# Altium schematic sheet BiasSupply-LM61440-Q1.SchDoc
size 431 x 279 mm; Date: Not shown in title block; ApprovedBy: Not shown in title block; CheckedBy: Not shown in title block; Author: Not shown in title block; CompanyName: Not shown in title block; Engineer: Not shown in title block; Organization: Not shown in title block; Address1: Not shown in title block; Address2: Not shown in title block; Address3: Not shown in title block; Address4: Not shown in title block; DocumentNumber: 2; Revision: Use project parameter SCH_Rev; SheetNumber: 2; SheetTotal: 3; PageSetup: Record=PageOptions¦CenterHorizontal=True¦CenterVertical=True¦PrintScale=1.00¦XCorrection=1.00¦YCorrection=1.00¦PrintKind=0¦BorderSize=5000000¦LeftOffset=0¦BottomOffset=0¦Orientation=2¦PaperLength=1000¦PaperWidth=1000¦Scale=100¦PaperSource=15¦PrintQuality=600¦MediaType=1¦DitherType=10¦PaperKind=Letter¦PrintScaleMode=1
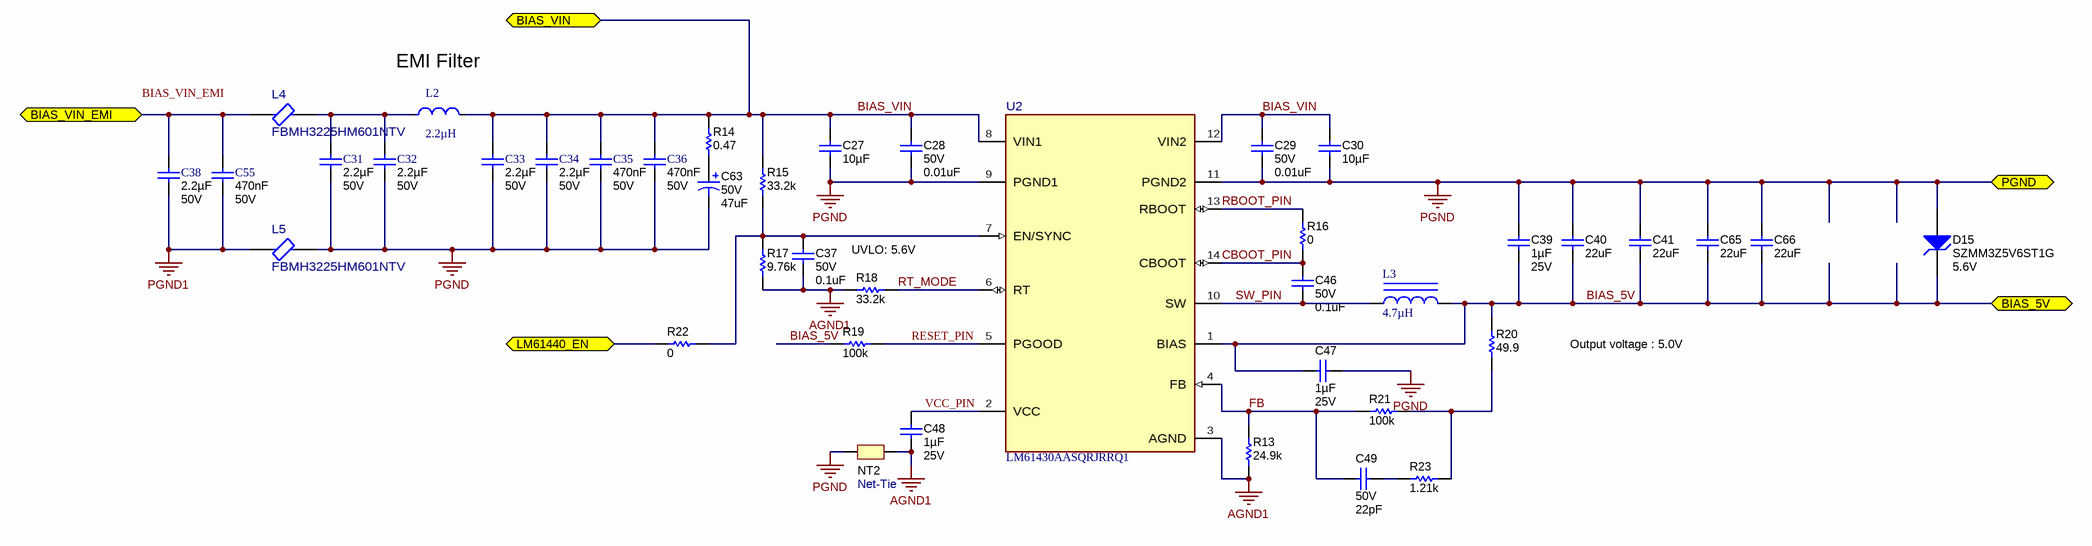
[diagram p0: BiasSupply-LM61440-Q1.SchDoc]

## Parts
C27  ValueDisplayed: 10µF  [1206_190]  (hidden comment: CGA5L1X7R1H106K160AC)
C28  VDC_V: 50V  ValueDisplayed: 0.01uF  [0402]  (hidden comment: CGA2B3X7R1H103K050BB)
C29  VDC_V: 50V  ValueDisplayed: 0.01uF  [0402]  (hidden comment: CGA2B3X7R1H103K050BB)
C30  ValueDisplayed: 10µF  [1206_190]  (hidden comment: CGA5L1X7R1H106K160AC)
C31  Cap_F: 2.2µF  VDC_V: 50V  [0805_HV]  (hidden comment: CF6)
C32  Cap_F: 2.2µF  VDC_V: 50V  [0805_HV]  (hidden comment: CF5)
C33  Cap_F: 2.2µF  VDC_V: 50V  [0805_HV]  (hidden comment: CF4)
C34  Cap_F: 2.2µF  VDC_V: 50V  [0805_HV]  (hidden comment: CF3)
C35  Cap_F: 470nF  VDC_V: 50V  [0603]  (hidden comment: CF2)
C36  Cap_F: 470nF  VDC_V: 50V  [0603]  (hidden comment: CF1)
C37  VDC_V: 50V  ValueDisplayed: 0.1uF  [0402]  (hidden comment: GCM155R71H104KE02D)
C38  Cap_F: 2.2µF  VDC_V: 50V  [0805_HV]  (hidden comment: CF6)
C39  Cap_F: 1µF  VDC_V: 25V  [0603S]  (hidden comment: CGA3E1X7R1E105K080AC)
C40  ValueDisplayed: 22uF  [1206_180]  (hidden comment: GCM31CR71A226KE02L)
C41  ValueDisplayed: 22uF  [1206_180]  (hidden comment: GCM31CR71A226KE02L)
C46  VDC_V: 50V  ValueDisplayed: 0.1uF  [0402]  (hidden comment: GCM155R71H104KE02D)
C47  Cap_F: 1µF  VDC_V: 25V  [0603S]  (hidden comment: CGA3E1X7R1E105K080AC)
C48  Cap_F: 1µF  VDC_V: 25V  [0603S]  (hidden comment: CGA3E1X7R1E105K080AC)
C49  VDC_V: 50V  ValueDisplayed: 22pF  [0402]  (hidden comment: CGA2B2NP01H220J050BA)
C55  Cap_F: 470nF  VDC_V: 50V  [0603]  (hidden comment: CF2)
C63  VDC_V: 50V  ValueDisplayed: 47uF  [SM_RADIAL_E]  (hidden comment: EEE-FK1H470P)
C65  ValueDisplayed: 22uF  [1206_180]  (hidden comment: GCM31CR71A226KE02L)
C66  ValueDisplayed: 22uF  [1206_180]  (hidden comment: GCM31CR71A226KE02L)
D15  SZMM3Z5V6ST1G  value 5.6V  [SOD-323]
L2  Ind_H: 2.2µH  [FP-744316220_SMD2-MFG]  (hidden comment: 744316220)
L3  ValueDisplayed: 4.7µH  [WE-XHMI_6060]  (hidden comment: 74439346047)
L4  FBMH3225HM601NTV  [FP-FBMH3225HM601NTV_1210-MFG]
L5  FBMH3225HM601NTV  [FP-FBMH3225HM601NTV_1210-MFG]
NT2  Net-Tie  [Net-Tie_10mil]  (net tie, no BOM)
R13  ValueDisplayed: 24.9k  [0402]  (hidden comment: CRCW040224K9FKED)
R14  ValueDisplayed: 0.47  [0805_HV]  (hidden comment: ERJ-6RQFR47V)
R15  ValueDisplayed: 33.2k  [0402]  (hidden comment: CRCW040233K2FKED)
R16  ValueDisplayed: 0  [0402]  (hidden comment: CRCW04020000Z0ED)
R17  ValueDisplayed: 9.76k  [0402]  (hidden comment: CRCW04029K76FKED)
R18  ValueDisplayed: 33.2k  [0402]  (hidden comment: CRCW040233K2FKED)
R19  ValueDisplayed: 100k  [0402]  (hidden comment: CRCW0402100KDHEDP)
R20  ValueDisplayed: 49.9  [0402]  (hidden comment: CRCW040249R9FKED)
R21  ValueDisplayed: 100k  [0402]  (hidden comment: CRCW0402100KDHEDP)
R22  ValueDisplayed: 0  [0402]  (hidden comment: CRCW04020000Z0ED)
R23  ValueDisplayed: 1.21k  [0402]  (hidden comment: CRCW04021K21FKED)
U2  LM61430AASQRJRRQ1  [RJR0014A-MFG]

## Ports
BIAS_5V (bidir), BIAS_VIN (bidir), BIAS_VIN_EMI (bidir), LM61440_EN (bidir), PGND (bidir)

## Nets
AGND1: C37.2 C48.2 NT2.2 R13.1 R17.1 R18.1 U2.3(AGND)
PGND: C27.2 C28.2 C29.2 C30.2 C31.2 C32.2 C33.2 C34.2 C35.2 C36.2 C39.2 C40.1 C41.1 C47.2 C63.2(-) C65.1 C66.1 D15.2(A) L5.2 NT2.1 U2.9(PGND1) U2.11(PGND2) ; port PGND
PGND1: C38.2 C55.2 L5.1
BIAS_5V: C39.1 C40.2 C41.2 C47.1 C65.2 C66.2 D15.1(K) L3.2 R19.1 R20.2 U2.1(BIAS) ; port BIAS_5V
BIAS_VIN: C27.1 C28.1 C29.1 C30.1 C33.1 C34.1 C35.1 C36.1 L2.2 R14.2 R15.2 U2.8(VIN1) U2.12(VIN2) ; port BIAS_VIN
BIAS_VIN_EMI: C38.1 C55.1 L4.1 ; port BIAS_VIN_EMI
CBOOT_PIN: C46.1 R16.1 U2.14(CBOOT)
FB: C49.2 R13.2 R21.1 U2.4(FB)
LM61440_EN: R22.1 ; port LM61440_EN
RBOOT_PIN: R16.2 U2.13(RBOOT)
RESET_PIN: R19.2 U2.5(PGOOD)
RT_MODE: R18.2 U2.6(RT)
SW_PIN: C46.2 L3.1 U2.10(SW)
VCC_PIN: C48.1 U2.2(VCC)
NetC31_1: C31.1 C32.1 L2.1 L4.2
NetC37_1: C37.1 R15.1 R17.2 R22.2 U2.7(EN/SYNC)
NetC49_1: C49.1 R23.2
NetC63_1: C63.1(+) R14.1
NetR20_1: R20.1 R21.2 R23.1

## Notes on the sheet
- (near L2) EMI Filter
- UVLO: 5.6V
- Output voltage : 5.0V
- Labels drawn without touching a wire or pin: BIAS_VIN_EMI

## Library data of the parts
C27 C30 = CMP-0085950-1: CAP, CERM, 10 µF, 50 V,+/- 10%, X7R, AEC-Q200 Grade 1, 1206; Manufacturer: TDK; SizeZ_mm: 1.9; Value: 10uF; Value2: 50V; Cap_Case: 1206; AEC Grade: 1; TaMin_C: -55°C; U/M: EA; SizeArea_mm2: 5.12; TaMax_C: 125°C; AEC Qualified: Y; AEC Category: Q200; SizeX_mm: 3.2; SizeY_mm: 1.6; Polarized: N; SizeAreaWB_mm2: 10.92
C28 C29 = CMP-0006324-2: CAP, CERM, 0.01 uF, 50 V, +/- 10%, X7R, AEC-Q200 Grade 1, 0402; Manufacturer: TDK; TaMin_C: -55°C; ESR_ohm: 0.333065; Polarized: N; SizeAreaWB_mm2: 3; Value1: 0.333065 ohm; U/M: EA; Value: 0.01uF; TaMax_C: 125°C; SizeZ_mm: 0.6; SizeX_mm: 1; SizeY_mm: 0.5; AEC Qualified: Y; Cap_F: 10nF; IRMS_A: 323.373mA; AEC Category: Q200
C31-C34 C38 = CMP-0007977-2: CAP, CERM, 2.2 uF, 50 V, +/- 10%, X7R, AEC-Q200 Grade 1, 0805; Manufacturer: TDK; PartNumber: CGA4J3X7R1H225K125AB; TaMin_C: -55°C; ESR_ohm: 3.288m; Polarized: N; SizeAreaWB_mm2: 6.75; Value1: 0.003288 ohm; U/M: EA; Value: 2.2uF; TaMax_C: 125°C; SizeZ_mm: 1.45; SizeX_mm: 2; SizeY_mm: 1.25; Cap_Case: 0805; SizeArea_mm2: 2.5; CompType: Capacitor; AEC Qualified: Y; IRMS_A: 3.60029A; AEC Grade: 1; AEC Category: Q200
C35 C36 C55 = CMP-0007097-4: CAP, CERM, 0.47 uF, 50 V, +/- 10%, X7R, AEC-Q200 Grade 1, 0603; Manufacturer: TDK; PartNumber: CGA3E3X7R1H474K080AE; TaMin_C: -55°C; Polarized: N; SizeAreaWB_mm2: 4.68; Value1: Unknown; U/M: EA; Value: 0.47uF; TaMax_C: 125°C; SizeZ_mm: 1; SizeX_mm: 1.6; SizeY_mm: 0.8; SizeArea_mm2: 1.28; CompType: Capacitor; AEC Qualified: Y; AEC Category: Q200
C37 C46 = CMP-0006356-2: CAP, CERM, 0.1 uF, 50 V, +/- 10%, X7R, AEC-Q200 Grade 1, 0402; Manufacturer: MuRata; TaMin_C: -55°C; Polarized: N; SizeAreaWB_mm2: 3; Value1: Unknown; U/M: EA; Value: 0.1uF; TaMax_C: 125°C; SizeZ_mm: 0.6; SizeX_mm: 1; SizeY_mm: 0.5; AEC Qualified: Y; Cap_F: 100nF; AEC Category: Q200
C39 C47 C48 = CMP-0076705-2: CAP, CERM, 1 µF, 25 V,+/- 10%, X7R, AEC-Q200 Grade 1, 0603; Manufacturer: TDK; SizeAreaWB_mm2: 4.68; SizeArea_mm2: 1.28; AEC Qualified: Y; AEC Category: Q200; Value: 1uF; TaMax_C: 125°C; SizeZ_mm: 1.0; AEC Grade: 1; Polarized: N; TaMin_C: -55°C; SizeY_mm: 0.8; U/M: EA; SizeX_mm: 1.6; Cap_Case: 1.6x0.8x0.8mm
C40 C41 C65 C66 = CMP-0008811-3: CAP, CERM, 22 uF, 10 V, +/- 10%, X7R, AEC-Q200 Grade 1, 1206; Manufacturer: MuRata; SizeX_mm: 3.2; SizeArea_mm2: 5.12; Polarized: N; SizeY_mm: 1.6; Value2: 10V; TaMin_C: -55°C; SizeZ_mm: 1.8; Cap_Case: 1206; AEC Grade: 1; Value1: Unknown; U/M: EA; AEC Qualified: Y; SizeAreaWB_mm2: 10.92; AEC Category: Q200; Value: 22uF; Cap_F: 22µF; TaMax_C: 125°C
C49 = CMP-0006311-2: CAP, CERM, 22 pF, 50 V, +/- 5%, C0G/NP0, AEC-Q200 Grade 1, 0402; Manufacturer: TDK; TaMin_C: -55°C; Polarized: N; SizeAreaWB_mm2: 3; Value1: Unknown; U/M: EA; Value: 22pF; TaMax_C: 125°C; SizeZ_mm: 0.6; SizeX_mm: 1; SizeY_mm: 0.5; AEC Qualified: Y; AEC Category: Q200
C63 = CMP-0011184-1: CAP, AL, 47 uF, 50 V, +/- 20%, 0.68 ohm, AEC-Q200 Grade 2, SMD; Manufacturer: Panasonic; TaMin_C: -55°C; ESR_ohm: 0.68; Polarized: Y; SizeAreaWB_mm2: 118.45; U/M: EA; Value: 47uF; TaMax_C: 105°C; SizeZ_mm: 6.2; SizeX_mm: 9.5; SizeY_mm: 8.3; Cap_Case: E; SizeArea_mm2: 78.85; CompType: Capacitor; Cap_F: 47µF; IRMS_A: 195mA; AEC Grade: 2; AEC Category: Q200
D15 = CMP-0085742-1: Diode, Zener, 5.6 V, 300 mW, AEC-Q101, SOD-323; Manufacturer: ON Semiconductor; SizeAreaWB_mm2: 8.695; SizeY_mm: 1.35; SizeZ_mm: 1; AEC Qualified: Y; SizeArea_mm2: 3.645; Value1: 0.3W; Power_W: 300mW; RJA_CperW: 416; AEC Category: Q101; SizeX_mm: 2.7
L2 = CMP-0086950-1: 2.2µH Shielded Molded Inductor 7.5A 11.3mOhm Max 2-SMD; Manufacturer: Wurth Electronics; SizeZ_mm: 4.3mm; DCR_ohm: 0.0113; Symbol Name: SYM-744316220; AEC Grade: Grade 0; AEC Qualified: Yes
L3 = CMP-0085367-1: Inductor, Shielded, Hyperflux, 4.7 µH, 7.4 A, 0.0143 ohm, SMD; Manufacturer: Wurth Elektronik; DCR_ohm: 0.0143; Value2: 7.4A; SizeArea_mm2: 42.8925; SizeX_mm: 6.65; Isat: 14.7A @ 30% inductance drop; AEC Category: Q200; Value: 4.7uH; SizeY_mm: 6.45; SizeZ_mm: 6.1; AEC Qualified: N; Irms: 7.4A @ 40C rise; SizeAreaWB_mm2: 73.0925
L4 L5 = CMP-0093384-1: 600 Ohms @ 100 MHz 1 Power Line Ferrite Bead 1210 (3225 Metric) 3A 42mOhm; Manufacturer: Taiyo Yuden; AEC Grade: Grade 1; Tolerance_%: 30%; Test Frequency: 100MHz; DCR_ohm: 0.042; AEC Qualified: Yes; Impedance At Frequency: 600Ω @ 100MHz; SizeZ_mm: 2.8mm
NT2 = CMP-0078142-4: Single point connection between nets.
R13 = CMP-0026196-2: RES, 24.9 k, 1%, 0.063 W, AEC-Q200 Grade 0, 0402; Manufacturer: Vishay-Dale; Power_W: 63mW; TempCo: 100 ppm/C; Value_Code: 24k9; Value: 24.9k; EIA_Code: E96; SizeX_mm: 1; SizeY_mm: 0.5; SizeZ_mm: 0.6; Value2: 0.063W; AEC Qualified: Y; VDC_V: 50V; AEC Category: Q200; AEC Grade: 0
R14 = CMP-0021842-3: RES, 0.47, 1%, 0.125 W, AEC-Q200 Grade 0, 0805; Manufacturer: Panasonic; Power_W: 125mW; TempCo: 250 ppm/C; Value_Code: R470; Value: 0.47; EIA_Code: E96; SizeX_mm: 2; SizeY_mm: 1.25; SizeZ_mm: 1.45; Value2: 0.125W; SizeArea_mm2: 2.5; AEC Qualified: Y; AEC Category: Q200; AEC Grade: 0; SizeAreaWB_mm2: 6.75
R15 R18 = CMP-0026298-2: RES, 33.2 k, 1%, 0.063 W, AEC-Q200 Grade 0, 0402; Manufacturer: Vishay-Dale; Power_W: 63mW; TempCo: 100 ppm/C; Value_Code: 33k2; Value: 33.2k; EIA_Code: E96; SizeX_mm: 1; SizeY_mm: 0.5; SizeZ_mm: 0.6; Value2: 0.063W; AEC Qualified: Y; VDC_V: 50V; AEC Category: Q200; AEC Grade: 0
R16 R22 = CMP-0026822-3: RES, 0, 5%, 0.063 W, AEC-Q200 Grade 0, 0402; Manufacturer: Vishay-Dale; Power_W: 63mW; TempCo: 200 ppm/C; Value_Code: 0000; Value: 0; EIA_Code: E24; SizeX_mm: 1; SizeY_mm: 0.5; SizeZ_mm: 0.6; Value2: 0.063W; AEC Qualified: Y; VDC_V: 50V; AEC Category: Q200
R17 = CMP-0026622-3: RES, 9.76 k, 1%, 0.063 W, AEC-Q200 Grade 0, 0402; Manufacturer: Vishay-Dale; AEC Category: Q200; AEC Qualified: Y; AEC Grade: 0; Value2: 0.063W; Value_Code: 9k76; SizeY_mm: 0.5; SizeZ_mm: 0.6; VDC_V: 50V; SizeX_mm: 1; Value: 9.76k; Power_W: 63mW; EIA_Code: E96; TempCo: 100 ppm/C
R19 R21 = CMP-0026768-2: RES, 100 k, 0.5%, 0.063 W, AEC-Q200 Grade 0, 0402; Manufacturer: Vishay-Dale; Power_W: 63mW; TempCo: 50 ppm/C; Value: 100k; EIA_Code: E192; SizeX_mm: 1; SizeY_mm: 0.5; SizeZ_mm: 0.6; Value2: 0.063W; AEC Qualified: Y; VDC_V: 50V; AEC Category: Q200; AEC Grade: 0
R20 = CMP-0026404-2: RES, 49.9, 1%, 0.063 W, AEC-Q200 Grade 0, 0402; Manufacturer: Vishay-Dale; Power_W: 63mW; TempCo: 100 ppm/C; Value_Code: 49R9; Value: 49.9; EIA_Code: E96; SizeX_mm: 1; SizeY_mm: 0.5; SizeZ_mm: 0.6; Value2: 0.063W; AEC Qualified: Y; VDC_V: 50V; AEC Category: Q200; AEC Grade: 0
R23 = CMP-0026079-3: RES, 1.21 k, 1%, 0.063 W, AEC-Q200 Grade 0, 0402; Manufacturer: Vishay-Dale; Power_W: 63mW; TempCo: 100 ppm/C; Value_Code: 1k21; Value: 1.21k; EIA_Code: E96; SizeX_mm: 1; SizeY_mm: 0.5; SizeZ_mm: 0.6; Value2: 0.063W; AEC Qualified: Y; VDC_V: 50V; AEC Category: Q200; AEC Grade: 0
U2 = CMP-0092866-1: 3-V to 36-V, Low EMI Synchronous Step-Down Converter; Manufacturer: Texas Instruments; AEC Grade: Grade 1; Output Type: AdjustableProgrammable; Switching Frequency: 200-2200kHz; Output Voltage: 1-34.2V; Max Duty Cycle: 98%; Number Of Outputs: 1; Max Supply Voltage: 36V; SizeZ_mm: 1mm; Min Supply Voltage: 3V; Standoff Height: 0mm; TJmax_C: +150°C; Switching Topology: Buck; AEC Qualified: Yes; Nominal Supply Current: 9uA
